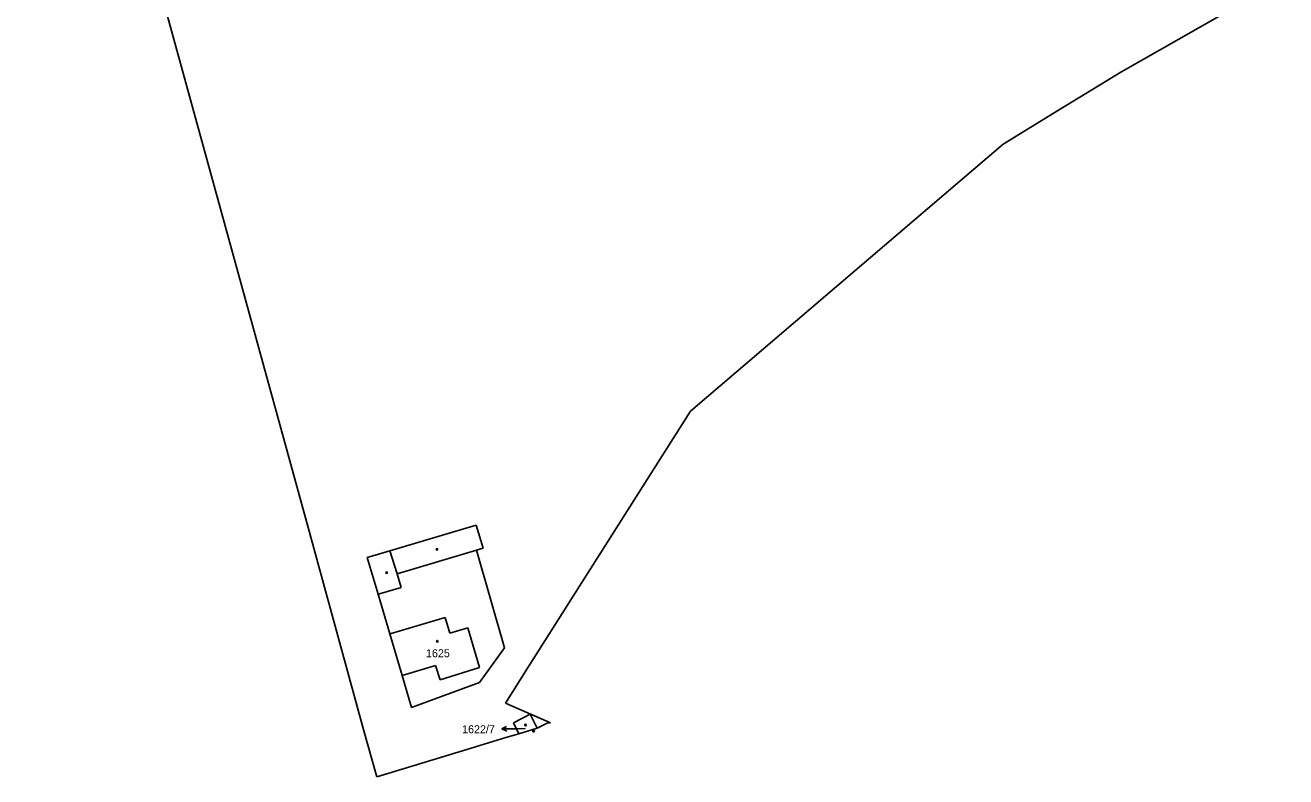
# Model space of a CAD drawing. Extents: x -763296 to -761805, y -1153670 to -1152034.
# Drawn here: x -762629.5 to -762361.8, y -1153552.8 to -1153393.1 of the extents above; entities that cross this region are included whole.
import ezdxf

# ---------------------------------------------------------------- set-up
doc = ezdxf.new("R2010")
doc.units = 0
for name, color, linetype in [('Vrstva 1', 7, 'Continuous'), ('Vrstva 13', 7, 'Continuous'), ('Vrstva 16', 7, 'Continuous'), ('Vrstva 19', 7, 'Continuous'), ('Vrstva 25', 7, 'Continuous'), ('Vrstva 4', 7, 'Continuous')]:
    doc.layers.add(name, color=color, linetype=linetype)

msp = doc.modelspace()

# ---------------------------------------------------------------- linework, layer by layer
at = {"layer": 'Vrstva 1'}
for p, q in [((-762552.09, -1153504.8), (-762533.74, -1153499.34)), ((-762533.74, -1153499.34), (-762532.28, -1153504.25)), ((-762532.28, -1153504.25), (-762533.65, -1153504.66)), ((-762533.65, -1153504.66), (-762527.76, -1153525.38)), ((-762556.9, -1153506.23), (-762552.09, -1153504.8)), ((-762554.58, -1153514.01), (-762556.9, -1153506.23)), ((-762552.08, -1153522.45), (-762554.58, -1153514.01)), ((-762549.44, -1153531.31), (-762552.08, -1153522.45)), ((-762527.76, -1153525.38), (-762533.07, -1153532.8)), ((-762547.48, -1153538.08), (-762549.44, -1153531.31)), ((-762533.07, -1153532.8), (-762547.48, -1153538.08)), ((-762522.25, -1153539.5), (-762525.82, -1153541.34)), ((-762520.78, -1153542.44), (-762522.25, -1153539.5)), ((-762525.82, -1153541.34), (-762524.71, -1153543.64))]:
    msp.add_line(p, q, dxfattribs=at)
at = {"layer": 'Vrstva 13'}
for p, q in [((-762629.54, -1153281.15), (-762569.44, -1153499.86)), ((-762384.53, -1153396.09), (-762361.78, -1153383.08)), ((-762396.81, -1153403.11), (-762384.53, -1153396.09)), ((-762410.03, -1153411.2), (-762396.81, -1153403.11)), ((-762421.81, -1153418.41), (-762410.03, -1153411.2)), ((-762488.24, -1153475.1), (-762421.81, -1153418.41)), ((-762513.14, -1153514.41), (-762488.24, -1153475.1)), ((-762569.44, -1153499.86), (-762557.58, -1153543.04)), ((-762522.84, -1153529.73), (-762513.14, -1153514.41)), ((-762527.55, -1153537.17), (-762522.84, -1153529.73)), ((-762527.55, -1153537.17), (-762517.94, -1153541.32)), ((-762520.78, -1153542.44), (-762518.56, -1153541.32)), ((-762518.56, -1153541.32), (-762517.94, -1153541.32)), ((-762557.58, -1153543.04), (-762555.91, -1153549.02)), ((-762527.43, -1153544.47), (-762535.71, -1153546.98)), ((-762524.71, -1153543.64), (-762527.43, -1153544.47)), ((-762524.71, -1153543.64), (-762520.78, -1153542.44)), ((-762554.85, -1153552.8), (-762535.71, -1153546.98)), ((-762555.91, -1153549.02), (-762554.85, -1153552.8))]:
    msp.add_line(p, q, dxfattribs=at)
at = {"layer": 'Vrstva 16'}
for p in [(-762528.28, -1153542.633), (-762523.35, -1153542.56)]:
    msp.add_line(p, (-762525.28, -1153542.59), dxfattribs=at)
msp.add_lwpolyline([(-762527.273, -1153543.118), (-762528.28, -1153542.633), (-762527.287, -1153542.118)], dxfattribs=at)
at = {"layer": 'Vrstva 25'}
for centre in [(-762542.06, -1153504.49), (-762552.78, -1153509.43), (-762541.99, -1153524.01), (-762523.26, -1153541.78), (-762521.56, -1153543.1)]:
    msp.add_circle(centre, 0.175, dxfattribs=at)
at = {"layer": 'Vrstva 4'}
for p, q in [((-762533.65, -1153504.66), (-762550.54, -1153509.67)), ((-762550.54, -1153509.67), (-762552.09, -1153504.8)), ((-762550.54, -1153509.67), (-762549.68, -1153512.56)), ((-762549.68, -1153512.56), (-762554.29, -1153513.93)), ((-762554.29, -1153513.93), (-762554.58, -1153514.01)), ((-762551.79, -1153522.37), (-762540.36, -1153518.97)), ((-762540.36, -1153518.97), (-762539.37, -1153522.29)), ((-762552.08, -1153522.45), (-762551.79, -1153522.37)), ((-762539.37, -1153522.29), (-762535.5, -1153521.13)), ((-762535.5, -1153521.13), (-762533.06, -1153529.55)), ((-762542.36, -1153529.13), (-762549.44, -1153531.31)), ((-762541.41, -1153532.23), (-762542.36, -1153529.13)), ((-762533.06, -1153529.55), (-762541.41, -1153532.23))]:
    msp.add_line(p, q, dxfattribs=at)

# ---------------------------------------------------------------- texts
at = {"layer": 'Vrstva 16'}
msp.add_text('1622/7', height=1.7, dxfattribs=at).set_placement((-762536.741, -1153543.55))
at = {"layer": 'Vrstva 19'}
for s, height, p in [('1625', 1.7, (-762544.406, -1153527.4)), ('1622/7', 0.1, (-762523.578, -1153542.56))]:
    msp.add_text(s, height=height, dxfattribs=at).set_placement(p)

doc.saveas('drawing.dxf')
